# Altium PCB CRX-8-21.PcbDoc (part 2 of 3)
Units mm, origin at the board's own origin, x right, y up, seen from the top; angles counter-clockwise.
Board outline 160.02 x 101.6 mm, 2 copper layers (TopLayer, BottomLayer), stack 1.535 mm thick; 254 components, 127 nets, 595 pads, 4322 vias.
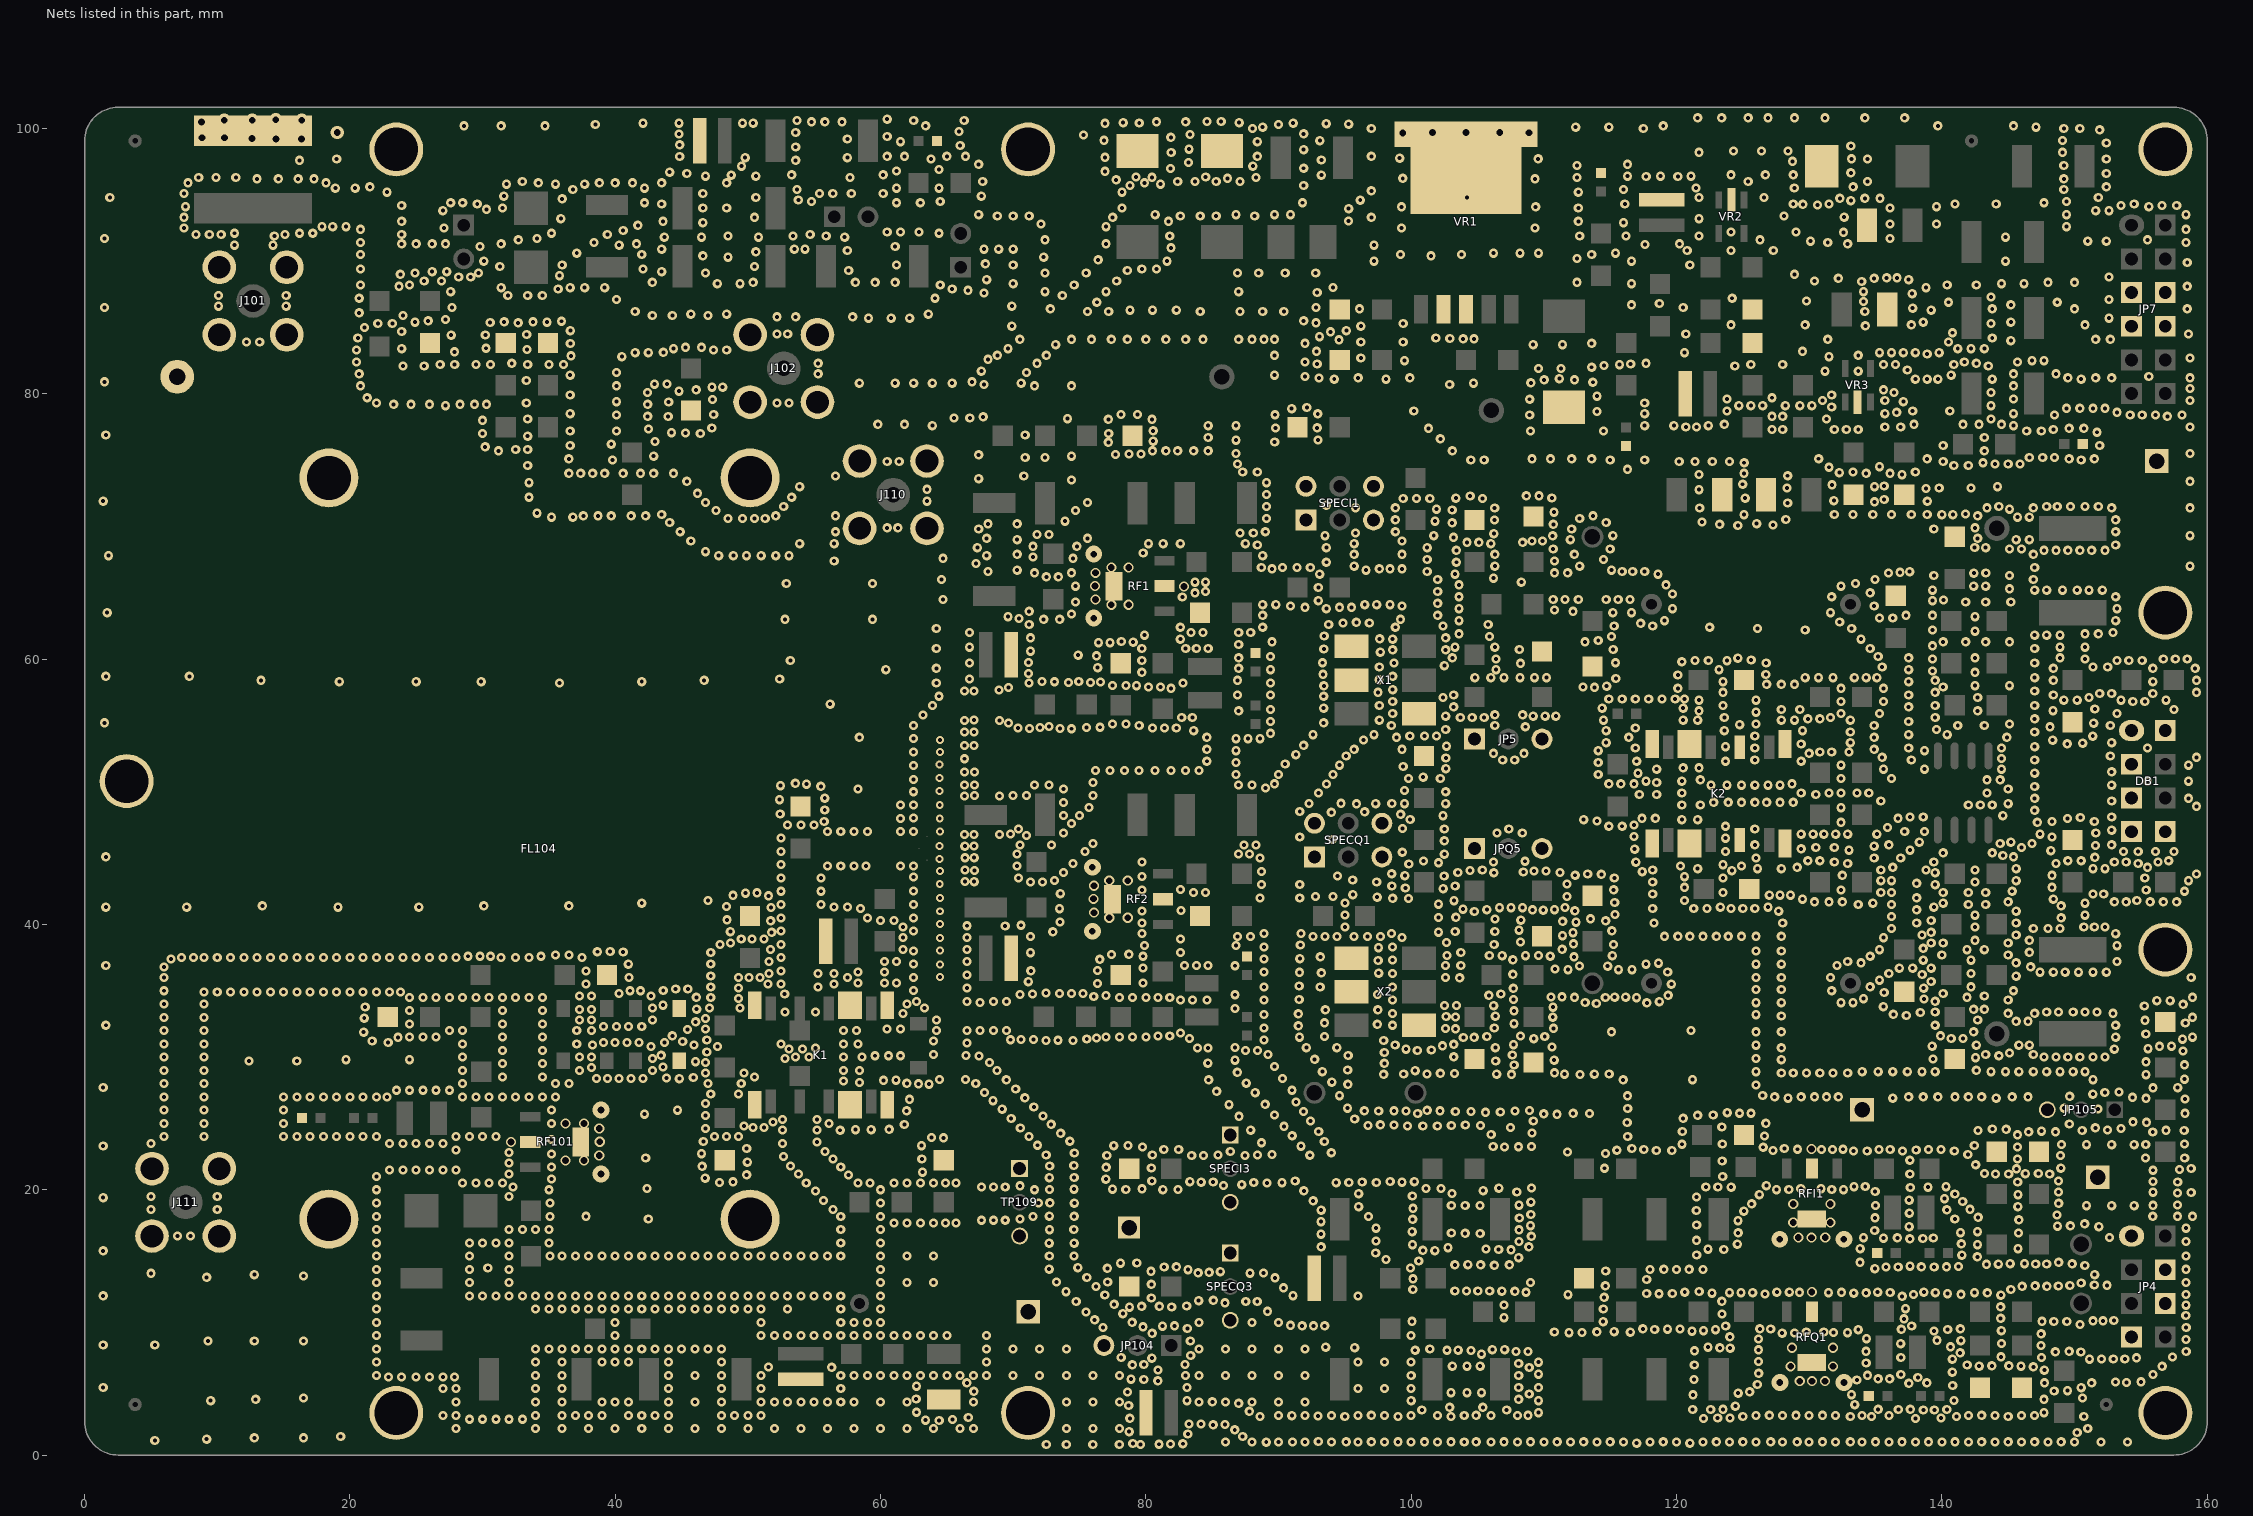
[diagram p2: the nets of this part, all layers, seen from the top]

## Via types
v1: diameter 0.7, hole 0.3, TopLayer to BottomLayer, 3209 vias
v2: diameter 0.68, hole 0.3, TopLayer to BottomLayer, 1006 vias
v3: diameter 0.762, hole 0.508, TopLayer to BottomLayer, 39 vias
v4: diameter 1, hole 0.508, TopLayer to BottomLayer, 20 vias
v5: diameter 1.27, hole 0.508, TopLayer to BottomLayer, 19 vias
v6: diameter 0.6, hole 0.3, TopLayer to BottomLayer, 19 vias
v7: diameter 1.27, hole 0.711, TopLayer to BottomLayer, 10 vias

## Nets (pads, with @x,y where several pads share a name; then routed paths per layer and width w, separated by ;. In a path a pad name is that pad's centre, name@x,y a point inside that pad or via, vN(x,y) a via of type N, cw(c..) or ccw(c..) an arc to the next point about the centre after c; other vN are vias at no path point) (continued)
GND: C6.2 C7.2 C10.2 C20.2 C21.2 C23.2 C30.1 C31.2 C32.2 C33.2 C34.2 C37.2 C38.2 C39.2 C40.2 C50.2 C51.2 C52.2 C53.2 C54.2 C61.2 C104.2 C105.2 C106.2 C107.2 C108.2 CQ7.2 CQ20.2 CQ21.2 CQ24.2 CQ40.2 D102.ANOD D104.CATH DB1.1 DB1.2 DB1.3 DB1.5 DB1.7 DB1.8 FL104.5 FL104.6 FL104.7 FL104.8 GAP1.2 J101.2 J101.3 J101.4 J101.5 J102.2 J102.3 J102.4 J102.5 J110.2 J110.3 J110.4 J110.5 J111.2 J111.3 J111.4 J111.5 JP4.1 JP4.4 JP4.6 JP4.7 JP5.1 JP5.3 JP7.5 JP7.6 JP7.7 JP7.8 JP104.3 JP105.3 JPQ5.1 JPQ5.3 K1.10 K1.11 K1.12 K1.13 K1.14 K1.15 K2.3 K2.6 K2.10 K2.11 K2.12 K2.13 K2.14 K2.15 LED1.2 LED2.2 LED3.1 LED101.2 R3.2 R4.2 R7.2 R10.1 R12.1 R17.2 R19.1 R20.2 R22.2 R26.2 R29.2 R31.2 R32.2 R42.2 R44.2 R60.1 R64.1 R80.1 R81.1 R101.2 R102.1 R104.2 R106.2 R110.2 R112.2 R204.2 R206.2 R209.2 R422.2 R442.2 RF1.2 RF1.4 RF2.2 RF2.4 RF101.2 RF101.4 RFI1.2 RFI1.4 RFQ1.2 RFQ1.4 RQ10.1 RQ12.1 RQ17.2 RQ19.1 RQ20.2 RQ22.2 RQ26.2 RQ29.2 RQ60.1 RQ64.1 SPECI1.1 SPECI1.2 SPECI1.5 SPECI1.6 SPECI3.1 SPECI3.3 SPECQ1.1 SPECQ1.2 SPECQ1.5 SPECQ1.6 SPECQ3.1 SPECQ3.3 TP6.TP TP7.TP TP12.TP TP13.TP TP81.TP TP82.TP TP83.TP TP84.TP TP85.TP TP86.TP TP87.TP TP88.TP TP99.TP TP107.TP TP109.1 TP109.3 TPQ6.TP VR1.2 VR1.3 VR1.6 VR1.6_1 VR2.2 VR3.2 X1.1 X1.4 X1.5 X2.1 X2.4 X2.5
  other v1: 72.5,0.8 74,0.8 76,0.8 78,0.8 79.6,0.8 81.854,0.827 79.02,0.87 82.783,0.852 117,0.9 121,0.9 89.074,0.972 91.045,0.978 95.1,1 97,1 99,1 101,1 103,1 104.9,1 107,1 109,1 111,1 113,1 115,1 119,1 123,1 125,1 127.1,1 129.1,1 131,1 133.1,1 135,1 137,1 139,1 141,1 143,1 145,1 147,1 149,1 92.998,1.016 5.3,1.1 9.2,1.2 12.8,1.3 16.5,1.3 19.3,1.4 87.3,1.4 83.16,1.581 150.2,1.7 78.746,1.762 86.7,1.9 85.069,2.284 64.421,2.609 63.391,2.632 65.428,2.677 78.791,2.769 123.1,2.8 66.618,2.837 95,2.9 99,2.9 103,2.9 125,2.9 133.1,2.9 134.7,2.9 141.1,2.9 145,2.9 150.7,2.9 92.973,2.937 91.001,2.968 97,3 104.9,3 108.8,3 127,3 129,3 131,3 143,3 109.6,3.2 147.7,3.2 62.705,3.226 87.8,3.3 100.8,3.4 107.2,3.4 138.609,3.401 139.437,3.401 121.218,3.439 122.574,3.427 136.725,3.439 140.379,3.427 123.503,3.452 135.206,3.452 137.629,3.452 102.9,3.6 105.4,3.6 124.433,3.69 78.7,3.73 133.436,3.799 87,3.9 85.006,4.017 9.5,4.1 83.1,4.1 100,4.1 109.6,4.1 140.919,4.117 12.9,4.2 108.1,4.2 147.7,4.2 62.682,4.233 16.5,4.3 150.6,4.3 121.243,4.544 133.184,4.554 124.646,4.67 103,4.7 104.2,4.7 105.3,4.7 78.608,4.76 125.512,4.77 67.03,4.805 148.465,4.833 149.47,4.858 150.499,5.084 1.4,5.1 83.1,5.1 108.1,5.1 109.6,5.1 62.705,5.194 140.819,5.247 126.09,5.323 137.516,5.41 66.503,5.446 138.872,5.448 147.737,5.448 151.291,5.448 153.927,5.473 153.099,5.511 155.007,5.523 80.9,5.6 133.596,5.652 79.844,5.698 121.319,5.699 78.883,5.721 135.206,5.749 136.072,5.749 138.194,5.85 100,6 108.1,6 134.39,6.013 136.914,6.076 155.911,6.076 109.6,6.1 126.19,6.164 140.793,6.252 147.725,6.402 56.32,6.613 51.561,6.636 146.896,6.653 156.614,6.691 103.1,6.7 104.2,6.7 105.2,6.7 142.815,6.704 145.967,6.704 143.769,6.729 145.05,6.729 121.344,6.792 141.911,6.792 78.979,6.804 79.845,6.829 82.947,6.829 108.1,6.9 134.302,6.942 109.6,7 126.178,7.055 140.793,7.231 151.127,7.231 152.031,7.244 152.923,7.244 153.789,7.244 80.448,7.306 154.668,7.332 78.137,7.357 136.914,7.357 147.511,7.357 157.393,7.394 144.46,7.407 83.373,7.507 105.3,7.6 141.384,7.708 148.553,7.784 150.474,7.771 107.9,7.8 108.8,7.8 158.423,7.809 134.277,7.821 149.595,7.821 121.356,7.859 104.506,7.884 100.3,7.9 102.7,7.9 103.539,7.909 126.178,7.934 106.113,7.947 107.042,7.947 101.4,8 124.043,8.06 123.265,8.085 95.741,8.097 93.557,8.135 122.373,8.135 140.655,8.16 147.473,8.261 1.4,8.3 5.3,8.3 136.901,8.399 144.498,8.411 9.3,8.6 12.8,8.6 16.5,8.6 83.348,8.6 141.434,8.625 139.638,8.65 158.41,8.713 126.178,8.75 134.314,8.775 124.018,8.914 147.486,9.14 80.473,9.177 127.961,9.19 128.89,9.202 111.901,9.221 132.883,9.228 112.875,9.24 131.841,9.24 110.79,9.271 116.516,9.265 129.782,9.278 131.106,9.269 113.992,9.29 115.298,9.297 121.174,9.334 139.412,9.353 122.034,9.378 144.485,9.378 122.938,9.447 133.699,9.454 118.349,9.472 119.316,9.485 136.951,9.479 140.442,9.466 120.258,9.497 127.095,9.504 117.458,9.516 126.278,9.516 141.396,9.516 83.122,9.541 76.769,9.617 158.423,9.617 79.782,9.667 81.251,9.717 123.704,9.73 137.73,9.73 82.156,9.742 91.786,9.742 92.64,9.742 93.481,9.742 90.907,9.78 150.412,9.843 78.966,10.006 114.475,10.05 148.44,10.069 149.42,10.069 100.055,10.081 147.549,10.081 151.391,10.119 152.157,10.119 152.961,10.144 76.141,10.194 137.152,10.27 144.435,10.307 106.992,10.358 158.397,10.521 123.428,10.634 78.263,10.659 75.488,10.785 89.174,10.835 114.482,11.011 137.265,11.036 78.769,11.144 81.942,11.161 144.435,11.174 79.684,11.213 81.013,11.211 83.072,11.237 158.4,11.3 77.61,11.362 85.96,11.475 74.747,11.576 87.53,11.576 88.396,11.576 123.416,11.588 83.976,11.638 85.081,11.663 80.41,11.839 114.551,11.889 137.014,11.965 1.4,12 91.096,12.015 76.907,12.065 144.447,12.053 111.826,12.09 137.868,12.103 158.4,12.1 141.446,12.115 126.668,12.141 117.753,12.172 118.682,12.159 119.68,12.172 140.429,12.166 122.675,12.203 133.36,12.203 134.302,12.228 143.43,12.228 123.993,12.241 124.859,12.241 125.738,12.241 131.464,12.241 136.11,12.254 139.513,12.241 142.463,12.241 108.662,12.272 120.622,12.279 127.559,12.279 128.501,12.279 129.274,12.264 132.431,12.266 135.168,12.279 138.646,12.279 73.981,12.316 121.708,12.323 106.835,12.354 107.814,12.341 103.288,12.36 105.027,12.367 105.912,12.36 100.124,12.473 145.201,12.48 90.367,12.605 76.241,12.706 146.055,12.718 147.913,12.718 114.639,12.756 147.034,12.756 148.779,12.743 149.646,12.781 152.446,12.794 151.491,12.819 80.41,12.869 150.499,12.969 158.4,13 73.266,13.045 77.121,13.043 117.746,13.233 100.13,13.283 89.74,13.359 75.551,13.384 9.2,13.4 16.5,13.5 12.8,13.6 151.517,13.597 5,13.7 87.844,13.71 88.861,13.723 83.938,13.735 84.767,13.773 85.608,13.823 80.385,13.848 114.664,13.88 83.173,13.974 119.046,13.999 120.954,13.999 158.4,14 72.713,14.011 134.946,14.05 77.098,14.073 30.4,14.1 99.954,14.099 74.873,14.124 81.377,14.175 135.796,14.175 136.713,14.175 139.425,14.175 82.294,14.187 138.458,14.187 140.354,14.187 141.258,14.212 137.604,14.237 106.27,14.307 150.776,14.288 103.288,14.338 107.4,14.338 104.267,14.35 105.234,14.344 143.367,14.376 144.259,14.388 147.072,14.401 147.9,14.401 149.821,14.413 145.15,14.426 146.23,14.426 78.082,14.462 79.318,14.485 133.825,14.531 148.804,14.526 100.569,14.633 98.108,14.746 108.103,14.878 142.677,14.941 72.726,15.003 74.584,15.003 158.4,15 141.509,15.066 121.52,15.079 97.324,15.229 1.4,15.4 100.877,15.43 101.781,15.405 107.526,15.468 106.596,15.499 123.566,15.493 122.373,15.518 105.636,15.537 145.741,15.556 133.848,15.56 102.773,15.631 93.218,15.694 108.869,15.7 100.098,15.857 142.689,15.857 124.583,15.895 141.471,15.92 72.713,15.97 74.597,15.97 108.135,16.096 158.4,16.1 97.342,16.133 121.507,16.184 137.592,16.297 138.571,16.322 135.608,16.347 139.362,16.36 134.099,16.384 136.65,16.372 152.647,16.397 109.051,16.485 93.205,16.648 104.073,16.711 105.196,16.705 103.03,16.736 124.646,16.749 145.778,16.736 141.409,16.761 100.073,16.837 142.689,16.837 134.942,16.925 108.128,16.975 72.738,16.987 74.571,17 97.349,17.107 158.4,17.1 137.541,17.213 151.83,17.213 148.716,17.251 149.683,17.276 109.001,17.289 121.52,17.339 150.763,17.427 93.205,17.59 124.633,17.665 145.803,17.728 100.111,17.766 140.982,17.791 42.5,17.8 108.147,17.873 134.967,17.879 142.74,17.916 74.597,17.992 96.777,17.979 155.899,17.992 157.757,17.992 37.8,18 72.726,18.004 158.9,18 148.679,18.092 109.013,18.13 137.554,18.23 125.073,18.381 121.494,18.431 93.218,18.456 140.379,18.482 142.124,18.519 100.136,18.595 96.043,18.726 145.728,18.72 104.073,18.808 134.992,18.808 150.9,18.8 152.8,18.8 154.5,18.8 103.024,18.814 105.19,18.814 155.911,18.821 108.128,18.839 157.77,18.846 125.663,18.934 74.609,18.984 148.804,18.971 72.763,19.009 109.013,19.059 141.572,19.109 92.609,19.166 137.541,19.21 140.203,19.323 1.4,19.4 121.507,19.448 100.086,19.524 126.241,19.624 145.741,19.624 140.982,19.687 96.043,19.699 103.074,19.725 157.757,19.762 155.924,19.812 158.8,19.8 107.959,19.838 148.792,19.825 134.98,19.875 91.905,19.919 105.429,19.925 81.277,20.001 127.534,20.001 132.594,20.001 72.738,20.026 78.494,20.023 82.419,20.026 128.463,20.013 131.703,20.013 74.584,20.039 77.487,20.045 79.707,20.068 130.899,20.076 42.4,20.1 101.116,20.101 102.246,20.089 129.367,20.089 106.609,20.114 109.064,20.126 137.629,20.164 122.21,20.202 124.119,20.189 138.96,20.189 123.114,20.214 133.385,20.227 140.316,20.227 134.227,20.239 126.768,20.302 85.847,20.315 87.228,20.378 89.137,20.516 90.254,20.528 94.348,20.534 47.854,20.549 88.132,20.553 95.302,20.553 97.374,20.553 84.165,20.566 96.306,20.578 99.307,20.566 48.884,20.595 83.311,20.604 85.069,20.591 100.237,20.604 145.716,20.591 157.782,20.591 98.416,20.616 155.924,20.629 148.792,20.654 80.448,20.666 91.259,20.666 76.984,20.801 46.778,20.869 72.726,20.905 74.597,20.93 123.478,20.993 49.913,21.121 137.592,21.181 144.046,21.181 145.037,21.181 148.126,21.194 143.217,21.219 146.293,21.206 147.273,21.219 63.162,21.327 155.924,21.47 157.92,21.533 145.632,21.579 158.8,21.6 114.576,21.621 148.973,21.624 80.41,21.633 77.007,21.693 46.55,21.762 72.751,21.784 74.571,21.834 142.551,21.884 49.959,22.082 123.441,22.173 137.592,22.223 63.117,22.311 145.701,22.311 42.3,22.4 155.346,22.399 158.309,22.399 77.052,22.585 83.449,22.587 84.34,22.587 87.479,22.575 148.95,22.585 85.433,22.613 92.358,22.6 72.487,22.625 80.486,22.625 88.409,22.625 89.513,22.663 141.961,22.65 46.504,22.723 114.651,22.726 74.609,22.763 93.984,22.788 111.776,22.851 86.362,22.889 133.348,22.914 134.377,22.926 137.039,22.926 140.944,22.926 118.481,22.964 119.649,22.964 127.27,22.952 115.505,22.977 138.069,22.989 81.352,23.027 82.469,23.039 117.539,23.027 130.937,23.027 131.765,23.039 135.256,23.039 136.11,23.039 138.998,23.027 139.94,23.027 129.116,23.052 132.557,23.052 49.913,23.112 116.635,23.102 128.124,23.102 126.529,23.203 79.753,23.226 107.03,23.228 145.701,23.226 106.176,23.253 108.084,23.24 109.064,23.253 1.4,23.3 91.698,23.284 63.094,23.318 77.579,23.318 71.834,23.353 78.654,23.341 142.452,23.341 150.9,23.4 152.8,23.4 154.5,23.4 155.371,23.404 120.415,23.429 149.019,23.409 123.453,23.441 158.297,23.441 88.716,23.542 46.641,23.638 74.27,23.655 93.456,23.642 64.741,23.913 63.849,23.935 71.194,24.006 116.321,24.019 126.64,24.05 91.033,24.069 145.701,24.141 106.025,24.157 73.58,24.257 109.101,24.283 146.548,24.37 148.561,24.37 155.899,24.358 93.029,24.396 120.44,24.396 147.509,24.416 142.726,24.462 150.575,24.458 158.272,24.458 56.961,24.485 87.9,24.49 152.483,24.496 156.903,24.483 58.105,24.53 59.295,24.53 60.645,24.553 144.854,24.553 143.802,24.576 153.5,24.609 70.541,24.659 151.567,24.672 107.494,24.697 123.416,24.722 90.418,24.779 99.722,24.797 100.877,24.797 101.969,24.81 96.746,24.835 103.024,24.835 105.221,24.848 98.705,24.873 104.079,24.873 97.675,24.898 61.79,24.919 72.864,24.935 149.608,24.961 126.731,25.011 116.284,25.074 155.422,25.086 154.404,25.124 92.414,25.174 109.202,25.174 95.741,25.337 69.85,25.362 120.502,25.387 87.027,25.532 72.249,25.563 121.595,25.614 89.696,25.626 122.763,25.626 110.985,25.689 42.2,25.7 100.488,25.739 109.993,25.727 112.215,25.764 113.433,25.752 124.74,25.766 125.61,25.766 158.322,25.764 123.825,25.812 105.598,25.84 106.716,25.852 103.325,25.902 104.506,25.902 97.55,25.94 99.609,25.94 107.821,25.927 61.973,25.949 96.47,25.953 98.705,25.953 102.17,25.953 101.203,25.99 108.926,25.978 44.7,26 69.172,26.078 151.769,26.089 116.321,26.128 95.202,26.153 149.219,26.153 71.558,26.241 86.268,26.417 88.992,26.436 68.482,26.718 62.179,26.819 158.335,26.844 128.4,26.9 136.3,26.9 144.1,26.9 155.396,26.894 70.88,26.932 154.379,26.97 127.4,27 129.4,27 130.4,27 131.3,27 132.2,27 137.5,27 138.6,27 139.7,27 141,27 142,27 143,27 145.3,27 146.5,27 149.633,27.045 116.309,27.083 94.599,27.095 126.5,27.1 151.378,27.208 88.239,27.315 67.829,27.334 152.282,27.334 153.35,27.371 85.339,27.415 70.189,27.597 155.911,27.685 157.782,27.698 1.4,27.7 126,27.9 95.227,27.949 63.648,27.962 62.856,27.987 61.978,28.024 67.176,28.012 87.567,28.037 94.021,28.112 60.22,28.25 61.161,28.263 69.486,28.288 84.73,28.288 115.982,28.288 121.2,28.3 151.4,28.3 64.439,28.313 66.397,28.313 158.297,28.338 44.833,28.375 43.872,28.421 45.886,28.466 155.384,28.677 97.926,28.702 107.557,28.702 112.718,28.69 99.433,28.727 101.191,28.727 106.439,28.715 111.562,28.715 113.81,28.715 114.927,28.727 103.263,28.765 102.195,28.778 110.805,28.81 127.9,28.8 128.8,28.8 129.8,28.8 130.8,28.8 131.8,28.8 132.9,28.8 86.889,28.847 93.306,28.903 126,28.9 134,28.9 135.2,28.9 136.3,28.9 137.4,28.9 138.5,28.9 139.5,28.9 143.7,28.9 144.8,28.9 145.8,28.9 146.9,28.9 147.9,28.9 148.9,28.9 149.9,28.9 150.8,28.9 100.299,28.979 142.6,29 95.214,29.029 43.598,29.244 107.761,29.405 158.297,29.418 84.673,29.537 97.976,29.531 155.384,29.644 46.046,29.656 12.4,29.7 16,29.7 106.365,29.702 86.726,29.763 110.782,29.771 19.7,29.8 24.5,29.8 127.9,29.8 92.728,29.832 139.34,29.862 126,29.9 142.543,29.954 147.7,30 148.6,30 149.5,30 150.4,30 151.4,30 152.3,30 103.208,30.022 144.3,30.1 43.46,30.137 95.252,30.121 107.624,30.16 143.3,30.2 146.9,30.2 145.1,30.3 97.976,30.347 158.184,30.46 100.462,30.503 101.514,30.526 99.615,30.594 153,30.6 155.535,30.636 92.1,30.711 94.398,30.711 106.342,30.709 127.9,30.7 110.622,30.755 156.413,30.812 102.361,30.846 139.271,30.823 157.318,30.824 45.932,30.915 98.791,30.915 126,30.9 142.6,30.9 145.8,30.9 146.6,30.9 107.715,30.938 103.208,30.961 66.51,31.063 22.889,31.098 43.712,31.098 45.085,31.166 21.676,31.212 97.926,31.251 158.149,31.35 109.239,31.389 140.7,31.4 141.6,31.4 103.928,31.477 23.621,31.487 91.585,31.502 104.744,31.49 153.1,31.5 158.9,31.5 93.469,31.553 105.699,31.553 110.068,31.553 44.3,31.6 108.248,31.59 139.9,31.6 155.38,31.739 21.035,31.876 115.1,31.9 126,31.9 127.9,31.9 142.4,31.9 121.1,32 45.451,32.082 103.338,32.13 102.59,32.15 110.721,32.168 106.264,32.193 91.497,32.356 1.6,32.4 139.5,32.4 153.1,32.4 97.449,32.469 107.745,32.519 158.355,32.562 93.469,32.582 46.069,32.654 145.6,32.7 146.5,32.7 155.312,32.768 142.7,32.8 21.081,32.928 158.9,33 103.338,33.022 110.671,33.009 102.635,33.066 106.339,33.085 127.9,33.1 137.326,33.134 126,33.2 136.342,33.226 91.497,33.26 145,33.3 147,33.3 152.9,33.3 138.379,33.363 139.5,33.4 147.9,33.4 148.8,33.4 149.9,33.4 150.8,33.4 151.7,33.4 107.758,33.486 93.532,33.562 97.487,33.562 46.138,33.615 142.4,33.6 143.2,33.6 110.696,33.763 21.15,33.775 135.587,33.798 155.266,33.844 106.213,33.876 43.598,33.912 158.195,33.981 113.961,34.039 117.765,34.089 113.119,34.114 126,34.1 127.9,34.1 132.4,34.1 133.3,34.1 118.707,34.177 139.5,34.2 156.204,34.256 157.211,34.256 145,34.3 91.56,34.34 107.708,34.34 138.653,34.37 134.1,34.4 116.987,34.478 112.316,34.503 114.639,34.491 141.9,34.5 158.9,34.5 46.115,34.507 110.545,34.528 115.342,34.516 116.171,34.516 111.361,34.541 143.2,34.6 105.849,34.654 119.372,34.654 97.462,34.717 52.774,34.759 106.753,34.754 140.1,34.8 135.655,34.874 43.62,35.011 131.7,35 145.4,35 126,35.1 127.9,35.1 44.559,35.125 45.474,35.125 107.695,35.181 138.63,35.194 93.142,35.282 134.6,35.3 142.2,35.3 91.56,35.357 119.611,35.495 71.144,35.684 139.2,35.7 135.3,35.8 103.652,35.972 41.035,35.995 126,36 127.9,36 131.6,36 158.8,36 145.6,36.1 138.516,36.224 107.657,36.236 136,36.3 142.2,36.3 97.55,36.324 93.23,36.349 91.585,36.387 147.4,36.4 148.4,36.4 149.3,36.4 150.3,36.4 151.4,36.4 152.4,36.4 119.335,36.412 71.332,36.497 76.352,36.528 111.813,36.588 115.631,36.588 116.648,36.588 110.834,36.638 136.8,36.7 137.8,36.7 139.2,36.7 146.7,36.8 112.68,36.864 114.814,36.851 1.6,36.9 103.74,36.902 132.1,36.9 40.989,37.002 117.702,37.002 126,37 127.9,37 118.644,37.077 133.9,37.1 145.6,37.1 132.9,37.2 153.2,37.2 97.512,37.278 138.6,37.3 142.2,37.3 107.657,37.329 76.524,37.373 91.61,37.416 93.155,37.555 112.278,37.555 134.6,37.6 110.483,37.605 102.698,37.655 105.887,37.655 106.854,37.642 108.612,37.642 109.591,37.655 115.166,37.642 140,37.7 145,37.7 77.415,37.732 78.713,37.748 71.3,37.873 103.74,37.881 146.6,37.9 40.6,37.917 38.655,37.94 39.616,37.963 126,38 127.9,38 135.3,38.1 141.9,38.1 143.2,38.1 111.377,38.123 138.6,38.2 97.537,38.245 153.2,38.4 91.648,38.446 106.251,38.484 115.254,38.484 112.24,38.534 139.2,38.6 140.1,38.6 145,38.6 102.66,38.634 108.242,38.672 142.5,38.8 146.6,38.8 135.6,39 71.3,39.093 119.1,39.1 120.1,39.1 121,39.1 122,39.1 123,39.1 123.9,39.1 124.9,39.1 126,39.1 127.9,39.1 111.4,39.153 138.5,39.2 145.6,39.2 153.1,39.3 112.203,39.375 51.79,39.404 139.2,39.4 102.057,39.413 48.678,39.45 72.989,39.437 103.313,39.463 106.301,39.463 115.128,39.513 108.127,39.565 136.2,39.7 146.9,39.7 148,39.7 148.9,39.7 142.5,39.8 150.7,39.8 151.5,39.8 152.3,39.8 69.392,39.875 70.581,39.937 118.3,40.1 128,40.1 138.1,40.1 145.6,40.1 112.429,40.166 73.521,40.188 111.422,40.228 114.664,40.267 51.721,40.274 108.265,40.32 139.2,40.3 48.426,40.343 106.314,40.405 113.521,40.417 149,40.5 102.057,40.518 103.363,40.53 136.2,40.6 142.5,40.7 150.8,40.7 115.358,40.754 104.757,40.97 127.7,41 145.6,41 112.338,41.029 109.955,41.07 105.699,41.108 109.152,41.095 110.809,41.108 138.1,41.1 103.903,41.146 73.49,41.188 118.2,41.2 121.3,41.2 122.3,41.2 124.1,41.2 125,41.2 125.9,41.2 106.653,41.259 107.532,41.259 108.386,41.259 51.744,41.281 111.6,41.271 1.6,41.3 7.7,41.3 19.1,41.3 25.2,41.3 123.3,41.3 126.9,41.3 139.4,41.3 48.38,41.349 13.4,41.4 30.1,41.4 36.5,41.4 149,41.4 133.7,41.5 136.2,41.5 142,41.5 143.3,41.5 102.057,41.522 42,41.6 134.8,41.6 140.1,41.6 150.8,41.6 115.335,41.647 130.4,41.7 131.5,41.7 132.5,41.7 145,41.7 153,41.7 153.9,41.7 155.7,41.7 156.7,41.7 157.7,41.7 103.225,41.786 47,41.8 120.6,41.8 154.7,41.8 129.5,41.9 148.4,41.9 98.604,41.962 99.797,41.949 138.1,42 97.437,42.05 111.738,42.112 51.561,42.15 48.884,42.196 127,42.2 127.8,42.2 128.6,42.2 95.603,42.238 118.2,42.3 151.4,42.3 152.2,42.3 73.552,42.314 49.822,42.356 50.691,42.379 123.5,42.4 135.4,42.4 136.2,42.4 140.1,42.4 142,42.4 143.3,42.4 145.3,42.5 158.3,42.5 115.267,42.608 132.4,42.6 155.4,42.6 102.409,42.69 99.559,42.753 120.6,42.8 148.3,42.8 98.541,42.891 103.313,42.904 139.5,43 111.738,43.042 138.1,43.1 97.399,43.192 118.2,43.2 142.5,43.2 66.36,43.243 67.059,43.225 135.4,43.3 136.2,43.3 145.6,43.3 158.6,43.3 95.591,43.356 115.313,43.5 123.5,43.5 155.3,43.5 120.6,43.6 94.448,43.644 99.521,43.669 102.484,43.657 132.5,43.7 148.3,43.7 112.361,43.706 114.329,43.775 113.299,43.798 159.2,43.8 98.529,43.82 106.226,43.895 139.5,43.9 103.514,43.921 111.211,43.908 108.448,43.958 117.418,43.981 109.265,44.021 110.169,44.034 124.168,44.05 67.075,44.071 104.43,44.071 66.372,44.096 105.36,44.096 118.2,44.1 135.4,44.1 138.8,44.1 142.5,44.1 121.6,44.2 126.1,44.2 127.9,44.2 145.6,44.2 151.4,44.2 152.3,44.2 129.1,44.3 136.3,44.3 155.5,44.3 120.3,44.4 124.9,44.4 123.5,44.5 99.822,44.561 132.9,44.6 148.6,44.6 154.8,44.6 102.057,44.649 116.937,44.69 106.2,44.7 131.9,44.7 139.4,44.7 153,44.7 153.9,44.7 156.3,44.7 108.587,44.762 100.927,44.774 129.9,44.8 130.8,44.8 149.5,44.8 150.5,44.8 157.1,44.8 126,45 134.9,45 136.9,45 66.36,45.026 67.059,45.035 151.536,45.056 1.6,45.1 145.4,45.1 144.6,45.2 102.5,45.3 140.1,45.4 143.8,45.4 99.333,45.44 123.7,45.5 153.7,45.5 154.8,45.5 156.1,45.5 157.5,45.5 148.218,45.56 133,45.6 137.6,45.6 116.846,45.674 129.4,45.7 130.5,45.8 131.9,45.8 146,45.8 66.352,45.899 67.05,45.904 134.9,45.9 151.582,45.949 125.9,46 136,46 152.8,46 144.4,46.1 146.8,46.1 138.3,46.2 145.2,46.2 102.5,46.3 94.071,46.394 123.7,46.5 148.31,46.59 116.8,46.635 129.4,46.8 130.3,46.8 131.1,46.8 132,46.8 132.9,46.8 135.1,46.8 147.4,46.8 106.465,46.884 108.373,46.896 151.605,46.887 137.2,47 138.7,47 152.8,47.1 102.5,47.2 107.356,47.185 125.9,47.2 99.345,47.223 135.9,47.3 114.9,47.4 115.9,47.4 123.7,47.4 116.8,47.5 132.4,47.7 147.2,47.7 55.748,47.757 148.31,47.757 151.49,47.757 114,47.8 99.923,47.901 113,47.9 120.4,47.9 121.6,47.9 149.477,47.985 117.4,48 118.4,48 136.7,48 150.438,48.054 137.6,48.1 138.6,48.1 152.8,48.1 102.4,48.2 144.6,48.2 99.207,48.303 52.43,48.329 93.984,48.453 96.495,48.491 147,48.6 55.794,48.626 132.4,48.8 159.2,48.9 120.4,49 121.8,49 142,49 142.9,49 143.8,49 95.88,49.094 97.324,49.106 99.5,49.1 102.6,49.1 145,49.1 94.712,49.131 98.541,49.119 122.8,49.2 123.9,49.2 124.9,49.2 125.9,49.2 126.8,49.2 127.8,49.2 128.8,49.2 135.4,49.3 152.8,49.3 52.385,49.404 147,49.5 158.6,49.5 55.794,49.519 117.2,49.8 118.5,49.8 130.5,49.8 120.4,49.9 129.4,49.9 131.5,49.9 132.4,49.9 133.6,49.9 134.5,49.9 143.4,49.9 102.6,50 99.5,50.1 58.3,50.2 145,50.2 147,50.4 55.497,50.411 52.453,50.457 122.6,50.5 123.8,50.5 124.9,50.5 125.9,50.5 126.9,50.5 127.8,50.5 152.8,50.5 54.421,50.571 89.7,50.6 114.9,50.6 115.8,50.6 116.8,50.6 128.7,50.6 53.575,50.64 118.5,50.7 117.7,50.8 120.4,50.8 155.5,50.8 158.6,50.8 121.8,50.9 143.4,50.9 144.4,50.9 99.8,51 102.2,51 132.4,51 136.2,51 100.9,51.1 86.8,51.3 90,51.3 94.1,51.3 114.1,51.3 117.1,51.4 147,51.4 152.8,51.5 118.5,51.7 135.6,51.7 138.7,51.7 144.5,51.7 102.613,51.738 120.5,51.8 121.7,51.8 99.4,51.9 94.6,52 132.4,52 158.6,52 90.5,52.1 86.8,52.2 114.1,52.2 84.6,52.3 117,52.3 123.7,52.3 129.4,52.3 106.9,52.4 107.8,52.4 125.9,52.4 137.7,52.4 147,52.4 144.5,52.5 102.613,52.539 135.5,52.6 159.2,52.6 95.1,52.7 152.7,52.7 91.3,52.8 106.2,52.9 108.5,52.9 130,52.9 130.8,53 131.7,53 133,53 86.8,53.1 114.1,53.1 138.7,53.1 84.6,53.2 95.7,53.2 99.3,53.2 134.9,53.2 116.9,53.3 125.9,53.3 137.5,53.3 144.5,53.3 155.5,53.3 123.7,53.4 147,53.4 102.658,53.432 91.9,53.5 129.4,53.6 149.454,53.615 150.621,53.66 114.7,53.7 133.1,53.7 152.8,53.7 96.4,53.9 148.355,53.889 86.8,54 87.7,54 88.6,54 58.4,54.1 84.6,54.1 98.9,54.1 116.4,54.1 134.9,54.1 144.9,54.1 151.376,54.187 99.9,54.2 101,54.2 101.9,54.2 125.9,54.2 92.6,54.3 97.2,54.3 137.5,54.3 140.4,54.3 89.4,54.4 133.1,54.5 147,54.5 83.6,54.6 114.7,54.6 123.6,54.6 129.5,54.6 102.6,54.7 139.6,54.7 80.5,54.8 81.4,54.8 82.3,54.8 116.9,54.8 108.6,54.9 148.15,54.896 79.5,55 98.5,55 106.3,55 134.9,55 141.2,55 143.2,55 152.7,55 124.763,55.056 126,55.1 145.1,55.1 151.445,55.171 1.5,55.2 93.4,55.2 89.4,55.3 137.5,55.3 97.6,55.4 114.5,55.4 120.5,55.4 121.6,55.4 127.9,55.4 128.9,55.4 133.1,55.4 129.9,55.5 130.8,55.5 147,55.5 82.7,55.6 83.5,55.6 103.7,55.6 104.6,55.6 105.5,55.6 123.6,55.6 131.6,55.6 139.5,55.6 102.6,55.7 109.2,55.7 110.1,55.7 110.9,55.7 106.3,55.8 108.4,55.8 98.6,55.9 132.4,55.9 135.3,55.9 153.2,55.9 126,56 87,56.1 121.7,56.1 142.7,56.1 148.378,56.109 89.4,56.2 127.9,56.2 129.3,56.2 157.5,56.2 151.536,56.246 93.4,56.3 114.4,56.3 120.5,56.3 103.2,56.4 137.5,56.4 97.6,56.5 123.5,56.5 139.5,56.5 147,56.5 56.2,56.6 98.6,56.8 132.4,56.8 135.6,56.8 154.4,56.8 155.3,56.8 121.7,56.9 126,56.9 149.2,56.9 150.2,56.9 153.5,56.9 156.9,56.9 114.9,57 115.9,57 116.9,57 117.9,57 118.9,57 119.9,57 120.6,57 102.4,57.1 142.7,57.1 151.1,57.1 93.4,57.2 86.9,57.3 89.4,57.3 103.2,57.3 137.5,57.3 148.4,57.3 151.9,57.4 152.8,57.4 155.9,57.4 97.5,57.5 123.5,57.5 139.5,57.5 159.2,57.5 147,57.6 98.6,57.7 81.9,57.8 120.1,57.8 132.4,57.8 135.6,57.8 113.825,57.871 112.956,57.894 80.2,57.9 81.1,57.9 140.1,57.9 114.74,57.962 79.3,58 93.414,57.985 142.5,58 145.1,58 126.8,58.1 127.9,58.1 128.9,58.1 35.8,58.2 64.2,58.2 82.8,58.2 89.4,58.2 19.2,58.3 25,58.3 29.9,58.3 42,58.3 123.5,58.3 137.5,58.3 155.9,58.3 13.3,58.4 46.7,58.4 86.9,58.4 139.5,58.4 148.4,58.4 159.2,58.4 97.578,58.443 52.4,58.5 66.7,58.5 115.427,58.534 104.8,58.6 106,58.6 107,58.6 108.2,58.6 109.3,58.6 110.2,58.6 129.7,58.6 130.7,58.6 131.8,58.6 133.4,58.6 134.3,58.6 135.1,58.6 147,58.6 1.6,58.7 7.9,58.7 98.6,58.7 120.1,58.8 126.731,58.832 93.345,58.855 79.7,59 142.5,59 139.3,59.1 60.4,59.2 89.4,59.2 106.4,59.2 123.2,59.2 137.5,59.2 64.2,59.3 87,59.3 148.4,59.3 155.9,59.3 159.1,59.3 76.366,59.358 97.601,59.404 135.5,59.4 151.4,59.4 152.5,59.4 102.5,59.5 66.7,59.7 98.7,59.7 108.242,59.679 126.754,59.701 147,59.7 93.322,59.724 115.404,59.724 71.155,59.75 120.4,59.8 53.2,59.9 79.7,59.9 121.4,59.9 122.4,59.9 123.802,59.885 153.2,59.9 154.1,59.9 155.1,59.9 125.633,59.93 106.4,60 139.3,60 150.8,60 156.7,60 157.6,60 158.5,60 124.626,60.068 87,60.1 103.1,60.1 137.5,60.1 142.5,60.1 148.9,60.1 89.4,60.2 135.2,60.2 76.274,60.251 74.9,60.3 97.67,60.525 71.3,60.6 98.6,60.7 102.6,60.7 108.15,60.731 115.221,60.731 93.414,60.754 64.2,60.8 79.7,60.8 83,60.8 83.8,60.8 84.7,60.8 134.6,60.8 147,60.8 66.7,60.9 103.3,60.9 106.3,60.9 148.9,60.9 150.8,60.9 139.3,61 87,61.1 76.435,61.235 77.304,61.235 79.043,61.28 89.5,61.3 113.1,61.3 140.1,61.3 141.8,61.3 143.3,61.3 145.1,61.3 78.151,61.326 114.1,61.4 82.6,61.5 98.6,61.5 133.9,61.5 97.624,61.532 71.3,61.6 102.6,61.6 105.9,61.7 115.1,61.7 93.437,61.738 79.9,61.8 147,61.8 147.9,61.8 148.9,61.8 103.6,61.9 150.8,61.9 151.8,61.9 66.7,62 83.4,62 84.3,62 87,62 87.9,62 152.9,62 142.5,62.1 129.7,62.2 139.3,62.2 64.2,62.3 126.1,62.3 133.2,62.3 82.6,62.4 88.8,62.4 98.8,62.4 122.5,62.4 102.4,62.5 115.3,62.5 118.2,62.5 71.2,62.6 93.78,62.608 105.8,62.6 94.855,62.722 96.846,62.722 117.3,62.7 95.862,62.768 132.3,62.8 103.6,62.9 119.1,62.9 153.1,62.9 52.8,63 59.4,63 72.3,63 73.5,63 99.2,63 70.439,63.065 135.3,63.1 136.3,63.1 69.6,63.2 142.5,63.2 88.8,63.3 102,63.3 137.3,63.3 139.3,63.3 74.4,63.4 1.7,63.5 115.2,63.5 116.6,63.5 131.6,63.5 71.2,63.6 112.2,63.6 110.8,63.7 93.6,63.8 103.6,63.8 119.7,63.8 153.2,63.8 92,63.9 94.6,63.9 95.5,63.9 90.9,64 99.3,64 134.9,64 88.8,64.1 89.8,64.1 96.5,64.1 97.4,64.1 98.4,64.1 102,64.2 74.7,64.3 141.8,64.3 143.3,64.3 145.2,64.3 93,64.4 139.3,64.4 140.133,64.447 64.7,64.5 110.7,64.5 111.6,64.5 112.6,64.5 114.7,64.5 115.6,64.5 116.5,64.5 82.75,64.689 103.6,64.7 131.7,64.7 153.1,64.7 119.7,64.9 83.7,65 134.6,65 84.5,65.1 102,65.1 139.3,65.2 147,65.2 147.9,65.2 149.1,65.2 150.2,65.2 151.1,65.2 152.1,65.2 145.1,65.3 93,65.4 74.7,65.5 132.4,65.5 142.4,65.5 143.3,65.5 103.6,65.6 119.2,65.6 52.9,65.7 59.4,65.7 133.5,65.7 83.7,65.8 84.5,65.8 108.3,65.8 64.6,66 102,66 134.969,65.994 146.9,66 106.2,66.1 72.5,66.2 73.4,66.2 139.4,66.3 145.1,66.3 93.1,66.4 103.3,66.4 118.6,66.4 142.416,66.479 71.6,66.5 74.4,66.5 110.8,66.5 111.8,66.5 135.976,66.498 143.317,66.487 136.845,66.543 68.1,66.6 101.2,66.6 115.9,66.6 116.7,66.6 117.6,66.6 137.578,66.589 70.3,66.7 96.6,66.7 115.1,66.7 89.5,66.8 97.6,66.8 98.4,66.8 99.3,66.8 88.7,66.9 90.3,66.9 91.4,66.9 92.4,66.9 147,66.9 95.7,67 106.3,67 112.7,67 158.7,67 67.2,67.2 93.6,67.3 103.4,67.3 56.5,67.4 110.8,67.4 101.2,67.5 114.5,67.5 64.7,67.6 74.5,67.6 71.5,67.7 1.8,67.8 47.8,67.8 48.9,67.8 49.9,67.8 51,67.8 52.1,67.8 53.1,67.8 68,67.8 88.8,67.8 70.3,67.9 95.7,67.9 99.3,67.9 106.3,67.9 112.3,67.9 146.9,67.9 79.8,68 46.8,68.1 103.4,68.2 147.7,68.2 148.6,68.2 149.5,68.2 150.4,68.2 151.3,68.2 152.3,68.2 110.7,68.3 115,68.3 145.1,68.3 146,68.3 67.3,68.4 93.6,68.4 101.2,68.4 143.3,68.4 142.475,68.42 71.5,68.5 74.8,68.5 88.4,68.6 153.1,68.6 53.9,68.7 56.5,68.7 80.2,68.7 81.3,68.7 82.6,68.7 87.5,68.7 95.7,68.7 106,68.7 104.2,68.8 105.1,68.8 108.4,68.8 45.7,68.9 99.3,68.9 109.1,68.9 109.9,68.9 70.3,69 112,69 145.6,69 146.6,69 68,69.1 75.6,69.1 142.7,69.1 103.185,69.175 93.5,69.3 101.7,69.3 110.667,69.289 115.2,69.3 158.7,69.3 71.8,69.4 72.7,69.4 106.228,69.45 87.1,69.5 88.1,69.5 95.8,69.5 44.9,69.6 56.6,69.6 89,69.6 98.8,69.6 153.1,69.6 67.4,69.8 112.1,69.8 139.4,69.8 60.5,69.9 61.3,69.9 142.5,69.9 124.626,70.067 127.28,70.113 110.713,70.159 123.253,70.159 68.1,70.2 70.3,70.2 126.045,70.205 103.093,70.273 44.1,70.3 114.7,70.3 121.926,70.342 73.9,70.4 101.8,70.4 106.274,70.479 98.8,70.5 153.1,70.5 128.241,70.525 48.5,70.6 49.6,70.6 50.5,70.6 51.3,70.6 89.1,70.6 112.7,70.6 35.2,70.7 36.8,70.7 145.7,70.7 146.6,70.7 37.6,70.8 38.7,70.8 39.7,70.8 41.2,70.8 42.3,70.8 52.1,70.8 56.6,70.8 113.7,70.8 142.7,70.8 43.5,70.9 125.084,70.891 131.9,70.9 133.3,70.9 134.8,70.9 136.2,70.9 137.7,70.9 138.9,70.9 140.003,70.891 140.827,70.891 141.788,70.937 34.1,71 110.759,71.074 47.6,71.2 74.7,71.2 103.093,71.234 101.9,71.3 145.1,71.3 95.8,71.4 98.8,71.4 106.297,71.395 121.743,71.395 143.4,71.4 146.9,71.4 152.8,71.4 158.7,71.4 52.7,71.5 89.1,71.5 144.3,71.5 147.9,71.5 148.7,71.5 149.7,71.5 150.8,71.5 151.8,71.5 93.6,71.6 128.379,71.761 46.8,71.8 75.6,71.8 134.923,71.852 1.4,71.9 63.5,71.9 138.905,71.898 131.857,71.944 135.655,72.035 99.4,72.1 100.4,72.1 101.4,72.1 105.381,72.104 103.368,72.127 125.175,72.127 110.599,72.15 33.5,72.2 53.3,72.2 104.443,72.287 108.677,72.31 109.638,72.31 89.1,72.4 46.2,72.5 121.697,72.768 63.5,72.8 138.813,72.859 128.333,72.905 139.8,72.9 142.2,72.9 53.9,73 134.923,72.996 144.2,73 135.655,73.042 131.72,73.134 124.992,73.179 33.5,73.3 89.1,73.3 45.4,73.4 158.7,73.4 74.4,73.5 67.4,73.6 56.6,73.8 70.8,73.8 128.379,73.82 137,73.9 121.697,73.912 36.5,74 37.4,74 38.3,74 39.2,74 40.6,74 41.9,74 42.9,74 44.4,74 134.3,74 136.1,74 125.084,74.003 132.269,74.049 87.3,74.1 88.4,74.1 133.3,74.1 138,74.1 116.3,74.3 131.491,74.461 135.3,74.5 33.4,74.6 140.9,74.6 142,74.6 86.9,74.7 144,74.7 145,74.7 145.9,74.7 125.1,74.8 143.1,74.8 60.5,74.9 61.4,74.9 120.2,74.9 121.4,74.9 122.7,74.9 124,74.9 140.1,74.9 39.8,75 104.5,75 105.5,75 115,75 117.6,75 150.5,75 36.5,75.1 109.1,75.1 110.5,75.1 112.1,75.1 113.6,75.1 130.713,75.102 138.9,75.1 149.6,75.1 151.5,75.1 70.9,75.2 72.4,75.2 146.6,75.2 147.6,75.2 148.5,75.2 42.9,75.3 74.4,75.3 67.4,75.4 77.716,75.422 78.723,75.468 79.638,75.468 86.8,75.5 158.7,75.5 31.2,75.7 80.5,75.7 81.5,75.7 82.4,75.7 83.6,75.7 84.7,75.7 103.1,75.7 143.2,75.7 32.5,75.8 33.4,75.8 30.2,76 36.6,76.1 140.1,76.1 151.9,76.1 39.7,76.2 77.167,76.337 89.707,76.36 43,76.4 80.553,76.429 86.8,76.5 92.979,76.52 102.2,76.6 84.7,76.7 143.2,76.7 33.4,76.8 1.6,76.9 70.9,76.9 30,77 77.2,77 46.412,77.001 45.291,77.047 44.238,77.07 151.7,77.1 36.6,77.2 40.1,77.2 109,77.2 114.5,77.2 146.4,77.2 147.5,77.2 80.553,77.207 127.2,77.3 128,77.3 131.9,77.3 132.8,77.3 133.7,77.3 148.4,77.3 42.516,77.35 101.3,77.4 149.6,77.4 150.7,77.4 47.282,77.413 89.775,77.413 92.91,77.436 120.7,77.5 121.5,77.5 135.7,77.5 136.9,77.5 158.7,77.5 63.9,77.6 84.7,77.6 86.8,77.6 117.6,77.6 119.8,77.6 122.4,77.6 145.4,77.6 59.8,77.7 61.8,77.7 123.6,77.7 137.9,77.7 141.6,77.7 142.8,77.7 144.5,77.7 30,78 77.167,78.076 80.462,78.076 33.4,78.1 131.3,78.1 143.7,78.1 74.1,78.122 65.542,78.168 66.732,78.168 67.739,78.259 43.987,78.282 42.448,78.3 127.2,78.3 128,78.3 157,78.3 108.928,78.397 40.1,78.4 89.73,78.42 148.5,78.4 154.2,78.4 155.1,78.4 156.1,78.4 158.1,78.4 47.419,78.443 78.128,78.443 79.364,78.443 92.956,78.488 36.6,78.5 117.6,78.5 135.7,78.5 145.4,78.5 136.6,78.6 153.2,78.6 114.008,78.671 100.2,78.7 123.8,78.7 137.8,78.7 140.6,78.7 90.988,78.877 149.4,78.9 150.4,78.9 151.4,78.9 152.3,78.9 92.132,78.969 131.7,79 27.2,79.1 124.7,79.1 125.6,79.1 126.5,79.1 128.2,79.1 129.3,79.1 130.2,79.1 143.7,79.1 23.3,79.2 24.6,79.2 26,79.2 28.3,79.2 29.4,79.2 30.3,79.2 42.448,79.202 22,79.3 33.3,79.3 52.2,79.3 53.1,79.3 117.6,79.3 44.032,79.381 40.1,79.4 137.1,79.4 131,79.5 135.7,79.5 158.7,79.5 47.328,79.564 108.928,79.587 123.8,79.6 145.4,79.6 21.3,79.7 127.2,79.7 114.008,79.815 36.6,79.9 131.7,79.9 42.44,80.103 136.4,80.1 143.7,80.1 44.8,80.2 46.1,80.3 135.6,80.3 158.7,80.4 47.3,80.5 48.1,80.5 20.8,80.6 40.1,80.6 71.6,80.6 74.4,80.6 145.4,80.6 67.8,80.7 102.9,80.7 42.966,80.719 43.898,80.734 58.4,80.8 61.1,80.8 62.5,80.8 63.9,80.8 65.4,80.8 70.6,80.8 104.7,80.8 109.02,80.822 113.688,80.868 1.5,80.9 66.9,80.9 33.3,81 110.027,81.051 112.315,81.051 94.2,81.1 98.1,81.1 138,81.1 138.9,81.1 139.7,81.1 143.8,81.1 150.5,81.1 111.171,81.143 93.048,81.188 96,81.2 99.9,81.2 149.5,81.2 151.6,81.2 152.8,81.2 158.7,81.2 92,81.3 155.6,81.3 36.6,81.4 89.7,81.4 140.7,81.4 20.7,81.5 55.3,81.5 145.4,81.5 148.6,81.5 40.1,81.6 71,81.6 67.6,81.7 131.2,81.7 133.7,81.7 137.4,81.8 109.6,81.9 111.3,81.9 113.6,82 24,82.1 25.6,82.1 124.4,82.1 143.5,82.1 114.535,82.127 26.8,82.2 27.9,82.2 29.5,82.2 30.6,82.2 33.4,82.2 35,82.2 36.1,82.2 115.702,82.195 125.6,82.2 128,82.2 135.6,82.2 136.5,82.2 140.9,82.2 92.91,82.241 116.548,82.241 32.2,82.3 55.3,82.3 71.8,82.3 117.7,82.3 142.6,82.3 20.5,82.4 92,82.4 141.7,82.4 145.7,82.4 99.5,82.5 146.8,82.5 147.7,82.5 68.1,82.6 96.2,82.7 158.7,82.7 40.502,82.793 131.5,82.8 36.664,82.859 68.8,82.9 72.5,82.9 89.7,82.9 133.7,82.9 138.9,83 41.5,83.1 42.5,83.1 120.6,83.1 135.3,83.1 136.2,83.1 137.1,83.1 138,83.1 139.8,83.1 43.627,83.123 27.888,83.162 92.864,83.202 129.5,83.2 20.5,83.3 47.4,83.3 48.4,83.3 33.346,83.339 23.9,83.4 44.4,83.4 69.6,83.4 141.2,83.4 142.2,83.4 143.2,83.4 30.257,83.431 45.3,83.5 46.5,83.5 73.2,83.7 109.2,83.7 111.4,83.7 36.618,83.797 92,83.8 113.6,83.8 12.2,83.9 13.2,83.9 96.2,83.9 99.4,83.9 140.5,83.9 145.2,84 94.558,84.072 70.5,84.1 74.4,84.1 75.9,84.1 77.4,84.1 78.6,84.1 80,84.1 81.5,84.1 83,84.1 84.3,84.1 87,84.1 88,84.1 88.9,84.1 89.7,84.1 131.4,84.1 151.6,84.1 152.7,84.1 103.917,84.14 104.741,84.14 102.91,84.163 20.6,84.2 101.857,84.209 143.8,84.2 93.093,84.301 27.638,84.413 30.211,84.438 33.323,84.461 52.2,84.5 53,84.5 120.7,84.5 158.6,84.5 140.8,84.6 93.917,84.667 23.9,84.7 36.618,84.758 95.107,84.758 21.1,85 69.9,85.1 96.2,85.1 134.237,85.124 124.1,85.2 129.7,85.2 137.7,85.2 150.8,85.2 22.1,85.3 23.2,85.3 99.4,85.3 143.7,85.3 32.682,85.353 92.819,85.353 30.577,85.376 24.9,85.4 34.856,85.399 138.6,85.4 145.2,85.4 31.63,85.422 33.804,85.422 35.955,85.468 25.9,85.5 91.9,85.5 27.2,85.6 59.1,85.7 60.8,85.7 62.2,85.7 152.6,85.7 52.2,85.8 53.6,85.8 57.9,85.8 24,85.9 42.8,85.9 44.3,85.9 47,85.9 45.7,86 48.4,86 63.6,86 20.7,86.1 41.5,86.2 75.6,86.2 77.2,86.2 84.1,86.2 87.1,86.2 88.8,86.2 90.4,86.2 134.2,86.2 78.8,86.3 80.5,86.3 82.3,86.3 139.2,86.3 72.8,86.4 96.1,86.4 143.8,86.4 150,86.4 158.5,86.4 137.806,86.452 92.819,86.497 1.5,86.5 27.7,86.5 120.5,86.5 10.1,86.6 15.2,86.6 69.9,86.6 116.6,86.7 145.2,86.7 118.7,86.8 76.3,86.9 140.5,86.9 148.7,86.9 134.099,86.955 129.8,87 40.1,87.1 152.6,87.1 20.7,87.2 64.1,87.2 124.2,87.2 143.7,87.3 10.1,87.4 15.2,87.4 31.9,87.4 33.4,87.4 34.5,87.4 73.7,87.4 137.761,87.55 67.8,87.6 92.91,87.641 27.6,87.7 72.4,87.7 77,87.7 87,87.7 134.1,87.7 66.6,87.8 35.7,87.9 65.4,87.9 31.4,88 36.6,88 37.7,88 39.2,88 94.1,88.008 138.8,88 23.7,88.1 158.5,88.1 20.8,88.2 24.5,88.2 64.5,88.2 74.6,88.2 140.4,88.2 142.6,88.2 47.7,88.3 49.4,88.3 70,88.3 116.6,88.3 144.5,88.3 146.2,88.3 42.8,88.4 50.4,88.4 58.1,88.4 59.6,88.4 61.1,88.4 112.5,88.4 148,88.4 150,88.4 133.962,88.465 25.6,88.5 26.9,88.5 77.8,88.5 130.4,88.5 68,88.6 137.5,88.6 132.2,88.7 134.9,88.7 135.839,88.74 136.617,88.74 28.2,88.8 29.1,88.8 152.6,88.8 35.8,88.9 23.8,89 128.9,89 24.9,89.1 29.7,89.1 46.8,89.1 72.4,89.1 75.5,89.1 86.9,89.1 88.5,89.1 90.5,89.1 92.8,89.1 26.2,89.2 27.3,89.2 43.5,89.2 57.6,89.3 78.6,89.3 20.8,89.4 42.1,89.4 79.7,89.4 80.8,89.4 31.3,89.6 50.5,89.6 36,89.7 61.2,89.7 70,89.7 121,89.7 67.9,89.8 158.5,89.9 30.1,90 81.6,90 97.2,90 116.6,90 144.8,90 76.4,90.1 112.5,90.2 48.5,90.3 72.3,90.3 46.6,90.4 101.5,90.4 20.8,90.5 42,90.5 99.2,90.5 103.8,90.5 113.6,90.5 37.1,90.6 106.2,90.6 108.2,90.6 109.6,90.6 115.4,90.6 50.6,90.7 57.5,90.8 120.8,90.8 124.1,90.8 127.3,90.8 43.5,90.9 53.5,90.9 54.3,90.9 67.8,90.9 68.9,90.9 70,90.9 81.9,91 29.8,91.1 61.1,91.1 11.3,91.2 14.2,91.2 40.3,91.2 97.2,91.2 117.624,91.257 23.9,91.3 25,91.3 26.2,91.3 27.2,91.3 31.4,91.3 41.6,91.3 77,91.3 132.9,91.3 120.232,91.303 20.8,91.4 38.4,91.4 131.4,91.4 158.4,91.4 130.1,91.5 151,91.5 152.4,91.5 32.7,91.6 72.4,91.6 126.3,91.6 155.5,91.6 1.5,91.7 34.1,91.7 136.1,91.7 43.7,91.8 46.5,91.8 50.8,91.8 57.3,91.8 144.8,91.8 14.3,91.9 48.5,91.9 53.4,91.9 55.9,91.9 81.8,91.9 112.7,91.9 116.2,91.9 121.7,91.9 8.4,92 9.4,92 10.3,92 15.1,92 23.9,92 39.4,92 54.7,92 11.3,92.1 16.2,92.1 17.2,92.1 35.2,92.1 64.4,92.1 132.589,92.172 60.5,92.2 61.5,92.2 62.9,92.2 124.1,92.2 129,92.2 40.6,92.3 20.8,92.4 158.4,92.4 99.272,92.493 109.34,92.493 7.5,92.5 27.1,92.5 17.9,92.6 18.7,92.6 19.7,92.6 77,92.6 149.4,92.6 41.7,92.7 72.1,92.8 136.1,92.8 139.6,92.8 46.6,92.9 116,92.9 23.9,93 43.6,93 81.7,93 112.6,93 95.267,93.019 35.9,93.2 121.7,93.2 7.5,93.3 50.5,93.3 77.5,93.3 97,93.3 132.635,93.316 68.8,93.4 70,93.4 71.2,93.4 82.6,93.4 84.1,93.4 85.3,93.4 88.2,93.4 128.1,93.4 67.4,93.5 80.7,93.5 86.8,93.5 89.7,93.5 90.9,93.5 149.4,93.5 158.4,93.5 27,93.8 151.6,93.8 152.6,93.8 30.3,93.9 95.29,93.957 31.5,94 46.6,94 48.4,94 78.2,94 112.6,94 136.1,94 7.6,94.1 99.272,94.094 109.386,94.094 139.6,94.1 155.6,94.1 23.9,94.2 153.5,94.2 156.6,94.2 157.7,94.2 130.621,94.232 129.523,94.277 29.6,94.3 43.5,94.3 116.1,94.3 128.8,94.3 131.5,94.3 141,94.3 144.1,94.3 154.5,94.3 27.6,94.4 28.5,94.4 42.2,94.4 61.2,94.4 63,94.4 91.8,94.4 147.7,94.4 54.8,94.5 64.5,94.5 149.4,94.5 133.138,94.552 53.8,94.6 96.16,94.598 36,94.7 132.315,94.735 134.191,94.735 135.335,94.735 1.9,94.8 50.6,94.8 104.2,94.8 121.7,94.8 126.6,94.8 151.8,94.8 31.6,94.9 67.6,94.9 7.5,95.1 46.6,95.1 55.4,95.1 56.4,95.1 57.8,95.1 60.2,95.1 22.8,95.2 78.2,95.2 112.6,95.2 97,95.3 36.8,95.4 53.7,95.4 116,95.4 149.2,95.4 18.9,95.5 20.4,95.5 42.2,95.5 61.2,95.5 64.4,95.5 121.468,95.513 128.882,95.513 21.5,95.6 133.321,95.605 152.4,95.6 78.8,95.7 91.9,95.7 31.8,95.8 35.5,95.8 37.7,95.8 81.1,95.8 7.8,95.9 18.2,95.9 34.2,95.9 38.8,95.9 40,95.9 41.3,95.9 43.5,95.9 48.4,95.9 79.9,95.9 33,96 67.7,96 82.4,96 83.7,96 85.3,96 87.1,96 125.4,96 134.4,96 77.762,96.131 13,96.2 14.6,96.2 16.1,96.2 17.3,96.2 109.34,96.2 149.2,96.2 86.16,96.245 99.363,96.245 8.6,96.3 9.9,96.3 11.4,96.3 57.7,96.3 88.3,96.3 112.5,96.3 80.462,96.314 79.249,96.337 84.512,96.337 46.8,96.4 50.6,96.4 116.3,96.4 117.715,96.383 118.8,96.4 120.095,96.383 121.1,96.4 48.746,96.474 93.231,96.474 53.3,96.5 60.2,96.5 124.1,96.5 126.7,96.5 128.8,96.5 45.4,96.6 152.4,96.6 133.138,96.657 44.1,96.7 76.915,96.772 61.2,96.8 64.4,96.9 81.858,96.978 91.9,97 49.524,97.161 88.059,97.161 112.5,97.2 149.2,97.2 67.4,97.3 116.3,97.3 83.208,97.435 128.745,97.527 16.2,97.6 53.6,97.6 93.231,97.618 19,97.7 63.8,97.7 134.4,97.7 152.4,97.7 109.569,97.71 133.184,97.71 99.134,97.756 49.799,97.801 57.5,97.8 76.915,97.824 44.856,97.893 60.5,97.9 61.8,97.9 65,97.9 66.4,97.9 88.4,97.9 97,97.9 81.904,98.19 121.7,98.2 149.1,98.2 124.3,98.3 126.4,98.3 128.4,98.3 91.9,98.4 83.254,98.442 53.6,98.6 133.138,98.671 66,98.717 44.856,98.763 152.4,98.9 61.5,99 88.4,99 93.116,99.083 76.846,99.106 149.1,99.1 57.5,99.2 81.881,99.335 60.5,99.4 75.3,99.5 83.322,99.541 44.81,99.586 91.9,99.6 53.6,99.7 65.908,99.769 151.9,99.9 88.036,99.998 97,100 117.5,100 149.2,100 150.4,100 88.8,100.1 112.4,100.1 114.9,100.1 147.1,100.1 28.6,100.2 31.4,100.2 34.7,100.2 63.4,100.2 119,100.2 139.7,100.2 145.4,100.2 38.5,100.3 90,100.3 95.29,100.319 93.597,100.364 76.915,100.387 42.1,100.4 44.8,100.4 49.6,100.4 50.4,100.4 79.501,100.41 91.1,100.4 78.288,100.433 87.029,100.433 54.8,100.5 55.8,100.5 57.1,100.5 80.8,100.5 83,100.5 84.604,100.525 85.679,100.525 53.7,100.6 62.5,100.6 66.3,100.6 60.5,100.7 121.6,100.8 123.4,100.8 125.4,100.8 126.9,100.8 128.9,100.8 131.2,100.8 134.2,100.8 137.2,100.8
  other v2: 81,0.815 86,1 88,1 90,1 92,1 94,1 96,1 98,1 100,1 102,1 104,1 106,1 108,1 110,1 112,1 114,1 116,1 118,1 120,1 122,1 124,1 126,1 128,1 130,1 132,1 134,1 136,1 138,1 140,1 142,1 144,1 146,1 148,1 150,1 152,1 154,1 28,2 34,2 36,2 38,2 40,2 42,2 44,2 46,2 48,2 50,2 52,2 54,2 56,2 58,2 60,2 62,2 64,2 66,2 67,2 74,2 76,2 78,2 151,2 85.96,2.296 83.248,2.334 84.165,2.334 29,2.7 30,2.7 31,2.7 32,2.7 33,2.7 138.006,2.748 122.022,2.761 124.031,2.786 139.952,2.811 88.6,2.9 27,3 28,3 34,3 36,3 37,3 38,3 39,3 41,3 42,3 43,3 44,3 48,3 49,3 50,3 51,3 90,3 92,3 94,3 96,3 98,3 100,3 102,3 104,3 106,3 108,3 126,3 128,3 130,3 132,3 134,3 136,3 142,3 144,3 146,3 147,3 28,4 34,4 36,4 39,4 40,4 41,4 44,4 46,4 48,4 51,4 52,4 53,4 54,4 55,4 56,4 57,4 58,4 60,4 62,4 67,4 74,4 76,4 78,4 84,4 86,4 88,4 90,4 92,4 108.9,4.6 27,5 28,5 34,5 36,5 44,5 48,5 51,5 57,5 96,5 98,5 100,5 22.9,5.9 23.9,5.9 25,5.9 26,5.9 27,5.9 27.9,5.9 22,6 34,6 36,6 44,6 46,6 48,6 51,6 57,6 58,6 59,6 60,6 61,6 62,6 63,6 64,6 65,6 66,6 67,6 68,6 70,6 72,6 74,6 76,6 78,6 83,6 84,6 86,6 88,6 90,6 92,6 80.9,6.4 108.9,6.6 22,7 34,7 36,7 39,7 40,7 41,7 44,7 48,7 68,7 96,7 98,7 100,7 22,8 34,8 35,8 36,8 37,8 38,8 39,8 40,8 41,8 42,8 43,8 44,8 45,8 46,8 47,8 48,8 68,8 70,8 72,8 74,8 84,8 86,8 88,8 90,8 92,8 22,9 40,9 51,9 52,9 53,9 54,9 55,9 56,9 57,9 58,9 59,9 60,9 61,9 62,9 63,9 64,9 65,9 68,9 100,9 22,10 40,10 51,10 57,10 58,10 59,10 60,10 84,10 88,10 90,10 22,11 34,11 35,11 36,11 37,11 38,11 39,11 40,11 41,11 42,11 43,11 44,11 45,11 46,11 47,11 48,11 49,11 50,11 51,11 53,11 57,11 60,11 106.979,11.318 22,12 29,12 30,12 31,12 32,12 33,12 34,12 35,12 36,12 37,12 38,12 39,12 40,12 41,12 42,12 43,12 44,12 45,12 46,12 47,12 48,12 49,12 50,12 51,12 52,12 53,12 54,12 55,12 56,12 57,12 60,12 96,12 104.167,12.367 22,13 29,13 32,13 60,13 62,13 64,13 109,13 22,14 29,14 32,14 60,14 118,14 120,14 122,14 22,15 29,15 32,15 35.1,15 36,15 37,15 38,15 39,15 40,15 41,15 42,15 43,15 44,15 45,15 46,15 47,15 48,15 49,15 50,15 51,15 52,15 53,15 54,15 55,15 56,15 57,15 60,15 62,15 64,15 22,16 29,16 30,16 31,16 32,16 35,16 57,16 60,16 7,16.5 8,16.5 22,17 32,17 33,17 34,17 35,17 57,17 60,17 61,17.5 62,17.5 63,17.5 64,17.5 64.9,17.5 65.7,17.5 67.6,17.7 68.5,17.7 69.4,17.7 70.5,17.8 22,18 35.1,18 57,18 60,18 71.5,18 5,18.5 10,18.5 56.4,18.5 22,19 35.1,19 60,19 71.9,19 55.7,19.2 5,19.5 10,19.5 32,19.5 55.1,19.9 22,20 35,20 60,20 71.6,20 32.3,20.2 67.6,20.2 68.5,20.2 69.4,20.2 70.5,20.3 28.5,20.5 29.5,20.5 30.5,20.5 31.5,20.5 54.4,20.5 58.3,20.5 59.2,20.5 61,20.5 62,20.5 63,20.5 64,20.5 64.9,20.5 65.7,20.5 35.2,20.8 22,21 57.6,21.1 32,21.2 53.8,21.2 23,21.5 24,21.5 25,21.5 26,21.5 27,21.5 28,21.5 35.2,21.7 57,21.7 53.2,21.8 32,22 56.4,22.3 52.7,22.5 35.2,22.7 31.989,22.807 55.8,22.9 28,23 5,23.5 23,23.5 24,23.5 25,23.5 26,23.5 27,23.5 52.6,23.5 55.2,23.6 35.2,23.8 6,24 9,24 15,24 16,24 17,24 18,24 19,24 20,24 21,24 22,24 28,24 29,24 30,24 31,24 47.5,24 48.4,24 49.3,24 52.6,24.5 55.2,24.5 46.8,24.6 50.4,24.7 51.2,24.7 49.7,24.8 6,25 9,25 15,25 35.2,25 56.1,25 51.9,25.1 52.6,25.3 55.2,25.3 46.8,25.6 91.9,25.9 6,26 9,26 15,26 35.2,26 46.8,26.5 91.3,26.6 6,27 9,27 15,27 16,27 17,27 18,27 19,27 20,27 21,27 22,27 22.8,27 28.5,27 29.5,27 30.5,27 31.5,27 32.5,27 33.5,27 34.5,27 35.5,27 47.2,27.2 49.3,27.2 23.5,27.5 24.5,27.5 25.5,27.5 26.5,27.5 27.5,27.5 91,27.5 6,28 9,28 28.5,28 35.5,28 36.5,28 47,28 49.5,28 58.4,28.1 57.2,28.2 38.6,28.4 39.4,28.4 40.3,28.4 41.2,28.4 42.1,28.4 90.3,28.4 31.5,28.5 34.5,28.5 50.5,28.5 46.8,28.8 49.7,28.8 68.796,28.979 6,29 9,29 28.5,29 37.3,29 42.8,29 57.2,29 58.4,29 38.2,29.2 89.7,29.3 31.5,29.5 34.5,29.5 46.8,29.6 68.205,29.606 42.8,29.9 52.8,29.9 6,30 9,30 28.5,30 37.3,30 38.2,30 53.6,30 54.6,30 57.2,30 58.6,30 59.6,30.1 60.6,30.1 61.5,30.1 67.427,30.096 66.448,30.134 64,30.2 89.2,30.2 46.9,30.4 31.5,30.5 34.5,30.5 87.5,30.5 88.4,30.5 53.1,30.6 54.1,30.6 55.1,30.7 83.9,30.7 84.7,30.7 86.711,30.709 42.7,30.8 47.7,30.8 38.3,30.9 6,31 9,31 28.5,31 37.1,31 52.5,31 57.2,31 58.3,31 39.1,31.1 40,31.1 40.9,31.1 41.8,31.1 64,31.2 72.454,31.245 74.522,31.241 73.381,31.269 46.9,31.3 88.9,31.3 69.8,31.306 70.598,31.325 71.544,31.325 75.543,31.371 83.3,31.4 76.294,31.445 24.5,31.5 25.5,31.5 26.5,31.5 31.5,31.5 34.5,31.5 77,31.5 78,31.5 79,31.5 80,31.5 80.9,31.6 81.8,31.6 82.6,31.8 6,32 9,32 27.5,32 28.5,32 37.1,32 38.2,32 57.2,32 58.2,32 64.2,32 66.5,32 67.5,32 68.5,32 69.5,32 46.8,32.1 60.5,32.1 61.5,32.1 88.9,32.2 39.1,32.3 40.1,32.3 41,32.3 42,32.3 98.6,32.4 24.5,32.5 31.5,32.5 34.5,32.5 37.3,32.8 38.2,32.8 42.8,32.8 64.2,32.8 46.8,32.9 6,33 9,33 88.9,33.2 61.7,33.3 98.6,33.3 52.8,33.4 55.111,33.389 24.5,33.5 31.5,33.5 34.5,33.5 37.3,33.6 38.2,33.6 86.719,33.676 42.8,33.7 47.1,33.7 49.4,33.7 63.3,33.7 102.5,33.9 103.4,33.9 6,34 9,34 62,34 67.5,34.1 62.7,34.2 66.5,34.2 68.5,34.2 69.5,34.2 82.6,34.3 83.5,34.3 84.6,34.3 88.9,34.3 98.6,34.3 49.3,34.4 24.5,34.5 25.5,34.5 26.5,34.5 27.5,34.5 28.5,34.5 29.5,34.5 30.5,34.5 31.5,34.5 32.5,34.5 33.5,34.5 34.5,34.5 47.2,34.5 78,34.5 79,34.5 80,34.5 80.9,34.5 81.8,34.5 76.072,34.553 37.3,34.6 38.2,34.6 42.7,34.6 76.981,34.637 86.711,34.698 70.524,34.72 71.47,34.739 40.3,34.8 73.474,34.794 74.383,34.804 75.255,34.794 72.454,34.821 9,34.9 10,34.9 11,34.9 12,34.9 13,34.9 14,34.9 15,34.9 16,34.9 17,34.9 18,34.9 19,34.9 20,34.9 21,34.9 22,34.9 23,34.9 23.8,34.9 6,35 41.1,35 41.9,35 62.49,35.008 49.3,35.2 66.5,35.2 47.2,35.3 55.3,35.3 88.9,35.3 98.6,35.3 37.8,35.5 51.5,35.5 52.5,35.5 56.5,35.5 76.341,35.546 58.3,35.6 60.3,35.6 61.2,35.6 79.8,35.6 6,36 49.3,36 50.1,36 50.9,36 57.5,36 62.49,36.003 102.6,36 47.2,36.1 66.5,36.2 51.6,36.3 55.3,36.3 56.5,36.3 98.6,36.3 58.3,36.4 60.3,36.4 88.9,36.4 37.8,36.5 52.5,36.5 79.8,36.7 6,36.8 86.711,36.884 82.9,36.9 83.8,36.9 84.7,36.9 102.6,36.9 47.2,37 62.49,37.006 51.6,37.2 60.3,37.2 61.2,37.2 66.5,37.2 98.6,37.3 6.5,37.4 88.9,37.4 7.3,37.5 8.2,37.5 9,37.5 10,37.5 11,37.5 12,37.5 13,37.5 14,37.5 15,37.5 16,37.5 17,37.5 18,37.5 19,37.5 20,37.5 21,37.5 22,37.5 23,37.5 24,37.5 25,37.5 26,37.5 27,37.5 28,37.5 31.4,37.5 32.5,37.5 33.5,37.5 37.5,37.5 52.5,37.5 28.9,37.6 29.8,37.6 30.6,37.6 34.4,37.6 79.8,37.6 35.5,37.7 36.5,37.7 47.2,37.9 82.6,37.9 62.488,37.999 51.7,38.1 61.7,38.1 66.5,38.1 88.9,38.3 98.6,38.3 79.9,38.4 86.8,38.4 47.9,38.5 52.5,38.5 48.7,38.6 49.5,38.9 50.3,38.9 51.2,38.9 82.6,38.9 61.7,39 66.5,39 99.3,39 86.9,39.1 87.9,39.1 92.6,39.1 93.5,39.1 94.4,39.1 95.7,39.1 96.7,39.1 97.7,39.1 79.7,39.3 88.9,39.3 91.7,39.3 98.5,39.3 52.5,39.5 62.485,39.501 61.7,39.8 95,39.8 66.5,39.9 79.7,40.1 60,40.3 61,40.3 52.5,40.5 59,40.5 62.483,40.499 95,40.7 79.7,41 82.644,41.066 58.5,41.2 56.5,41.3 57.5,41.3 52.5,41.5 55.5,41.5 62.49,41.492 95,41.6 88.6,42 91.6,42 92.8,42.1 94.1,42.1 83.6,42.4 84.5,42.4 52.5,42.5 55.5,42.5 62.488,42.503 79.7,42.6 82.609,42.616 88.7,43 91.6,43 71.3,43.2 72.2,43.2 73.1,43.3 52.5,43.5 55.5,43.5 70.4,43.5 62.467,43.564 79.7,43.6 73.8,43.9 88.7,44 56,44.4 57,44.4 58,44.4 58.9,44.4 61.5,44.4 70.3,44.4 62.467,44.421 52.5,44.5 74.5,44.6 79.7,44.7 88.6,45 70.3,45.3 87,45.3 87.8,45.3 52.5,45.5 75.4,45.5 70.5,46 72.9,46 87.4,46 88.3,46 76,46.1 52.5,46.5 91.6,46.6 71,46.7 67.028,46.771 66.338,46.783 68.949,46.787 69.8,46.8 73.8,46.9 56,47 57,47 58,47 59,47 61.5,47 62.474,47.002 70.4,47.2 53,47.5 54,47.5 55,47.5 74.4,47.6 61.5,48 62.467,48.016 73.8,48.2 75,48.2 91.6,48.5 75.7,48.8 61.5,49 62.485,48.997 92.3,49.1 73.8,49.2 66.325,49.692 68.953,49.693 67.066,49.706 70,49.7 71,49.7 76,49.7 93,49.9 62.493,50 73.8,50.2 89,50.3 66.338,50.503 67.066,50.5 71.6,50.5 72.7,50.5 87,50.5 88,50.5 93.6,50.6 76,50.7 62.472,50.92 66.331,51.483 67.069,51.476 76.2,51.6 77.3,51.6 78.4,51.6 79.5,51.6 80.7,51.6 81.9,51.6 83,51.6 84,51.6 62.481,51.986 66.331,52.489 62.488,52.999 66.328,53.493 67.047,53.492 62.493,54.002 66.341,54.49 67.057,54.487 74.383,54.75 71.211,54.759 73.539,54.768 70.376,54.796 72.008,54.833 75.524,54.842 76.55,54.862 72.695,54.926 62.5,55 77.5,55.1 78.5,55.1 69.633,55.186 68.961,55.358 66.341,55.389 67.053,55.406 63.2,55.8 63.9,56.5 64.4,57.2 66.335,57.598 67.041,57.607 68.937,57.656 69.633,57.876 77.5,58 78.5,58 71.192,58.191 74.151,58.219 75.822,58.23 76.57,58.272 73.119,58.292 74.94,58.293 72.163,58.313 71.136,58.896
  other v3: 129.291,5.57 130.207,5.57 131.194,5.57 128.605,6.69 131.805,6.69 128.705,8.09 131.805,8.09 130.199,12.29 129.184,16.393 130.181,16.386 131.216,16.393 128.803,17.536 131.597,17.536 128.803,18.933 131.597,18.933 36.257,22.203 37.654,22.203 38.797,22.584 130.181,23.071 32.148,23.6 38.833,23.617 38.797,24.616 36.257,24.997 37.654,24.997 77.236,40.503 78.633,40.503 76.093,40.884 76.056,41.929 76.093,42.916 77.236,43.297 78.633,43.297 77.4,64.1 78.7,64.1 76.2,64.5 82.873,65.464 76.162,65.517 76.2,66.5 77.4,66.9 78.7,66.9
  other v4: 14.422,99.209 16.356,99.209 12.626,99.243 8.85,99.3 10.555,99.3 99.361,99.649 108.873,99.68 19.05,99.695 101.6,99.695 104.14,99.695 106.68,99.695 8.816,100.479 12.637,100.616 10.532,100.627 16.367,100.627 14.41,100.662
  other v5: 127.792,5.466 132.618,5.466 127.787,16.266 132.613,16.266 38.924,21.187 38.924,26.013 75.966,39.487 75.966,44.313 76.066,63.087 76.066,67.913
